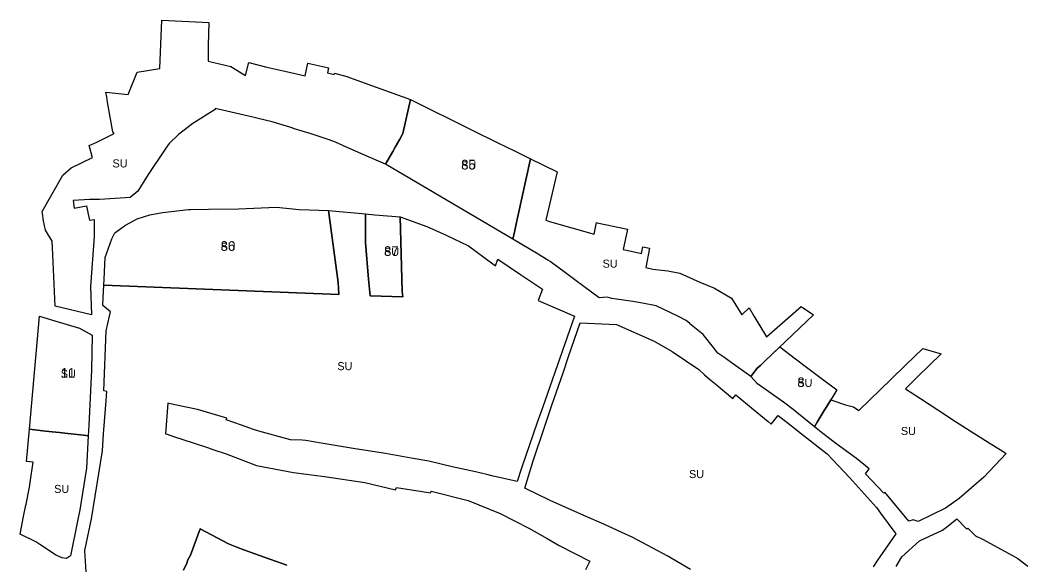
# Model space of a CAD drawing. Extents: x -545729 to -542727, y -1152416 to -1150952.
# Drawn here: x -544362 to -543736, y -1151290 to -1150952 of the extents above; entities that cross this region are included whole.
import ezdxf

# ---------------------------------------------------------------- set-up
doc = ezdxf.new("R2010")
doc.units = 0
for name, color, linetype in [('90480013', 7, 'Continuous'), ('90480023', 7, 'Continuous'), ('ID_navrh', 7, 'Continuous')]:
    doc.layers.add(name, color=color, linetype=linetype)

msp = doc.modelspace()

# ---------------------------------------------------------------- linework, layer by layer
at = {"layer": '90480013'}
for points in [[(-544281.81, -1151047.05), (-544286.37, -1151054.32), (-544288.69, -1151058.11), (-544293.42, -1151061.86), (-544302.75, -1151062.65), (-544312.53, -1151063.09), (-544318.75, -1151063.23), (-544328.84, -1151063.72), (-544328.3, -1151068.58), (-544320.64, -1151067.23), (-544319.5, -1151072.26), (-544318.73, -1151076.05), (-544315.73, -1151075.6), (-544315.73, -1151086.26), (-544317.99, -1151117.14), (-544317.35, -1151134.76), (-544340.06, -1151129.45), (-544341.74, -1151093.07), (-544341.92, -1151089.17), (-544346, -1151082.21), (-544347.27, -1151076.35), (-544347.85, -1151071.82), (-544348.07, -1151070.69), (-544342.02, -1151060.09), (-544335.18, -1151048.11), (-544330.07, -1151043.55), (-544316.92, -1151037.05), (-544317.11, -1151036.5), (-544318.86, -1151029.7), (-544314.12, -1151027.52), (-544303.38, -1151022.3), (-544304.25, -1151021.22), (-544307.45, -1151002.7), (-544308.03, -1150999.33), (-544308.64, -1150996.44), (-544294.75, -1150997.87), (-544289.15, -1150984.01), (-544275.03, -1150981.73), (-544273.79, -1150951.78), (-544244.73, -1150953.19), (-544245.06, -1150967.45), (-544245.1, -1150977.32), (-544231.07, -1150980.53), (-544221.95, -1150986.09), (-544219.85, -1150978.19), (-544208.58, -1150980.92), (-544197.54, -1150983.58), (-544184.95, -1150986.46), (-544183.27, -1150978.58), (-544173.93, -1150980.64), (-544170.39, -1150981.51), (-544171.09, -1150984.55), (-544166.85, -1150985.46), (-544166.56, -1150984.76), (-544159.03, -1150986.87), (-544145.91, -1150991.61), (-544119.4, -1151001.18), (-544124.2, -1151022.22), (-544126.02, -1151025.74), (-544128.94, -1151030.78), (-544130.55, -1151033.44), (-544135.01, -1151041.31), (-544148.39, -1151035.46), (-544158.87, -1151030.91), (-544166.12, -1151027.56), (-544169.93, -1151026.19), (-544181.06, -1151022.45), (-544192.4, -1151019.04), (-544192.34, -1151018.83), (-544205.37, -1151014.99), (-544214.12, -1151012.89), (-544217.31, -1151012.11), (-544227.99, -1151009.48), (-544236.21, -1151007.63), (-544240.8, -1151006.59), (-544240.68, -1151007.33), (-544254.64, -1151016.06), (-544263.54, -1151022.86), (-544269.25, -1151028.35), (-544269.15, -1151028.43), (-544271.34, -1151031.38)], [(-544055.89, -1151087.93), (-544054.67, -1151082.43), (-544054.09, -1151079.29), (-544052.62, -1151072.76), (-544045.08, -1151037.87), (-544028.46, -1151046.08), (-544035.43, -1151076.11), (-544033.15, -1151076.77), (-544019.44, -1151080.75), (-544005.53, -1151084.79), (-544004.04, -1151077.55), (-544003.66, -1151077.63), (-543984.82, -1151081.57), (-543987.45, -1151094.29), (-543982.64, -1151095.3), (-543976.17, -1151096.66), (-543975.37, -1151092.64), (-543971.13, -1151093.45), (-543973.4, -1151105.4), (-543969, -1151106.44), (-543959.81, -1151107.53), (-543952.27, -1151108.88), (-543939.98, -1151114.51), (-543930.93, -1151118.19), (-543920.31, -1151124.57), (-543913.95, -1151134.8), (-543909.27, -1151130.5), (-543906.23, -1151135.81), (-543898.64, -1151148.47), (-543877.03, -1151129.71), (-543869.4, -1151134.88), (-543899.56, -1151163.62), (-543902.11, -1151166.03), (-543904.57, -1151168.23), (-543905.39, -1151169.33), (-543905.59, -1151169.6), (-543908.28, -1151173.21), (-543920.47, -1151164.49), (-543925.06, -1151161.21), (-543928.69, -1151158.64), (-543931.37, -1151155.21), (-543937.89, -1151147.01), (-543946.19, -1151140.41), (-543946.15, -1151140.23), (-543948.46, -1151138.26), (-543953.58, -1151135.75), (-543966.97, -1151129.16), (-543975.61, -1151127.67), (-543981.61, -1151126.57), (-543994.53, -1151124.74), (-543997.51, -1151123.83), (-544002.35, -1151124.26), (-544016.68, -1151113.74), (-544023.35, -1151108.8), (-544032.91, -1151101.71), (-544034.19, -1151100.86), (-544037.9, -1151098.61), (-544040.31, -1151097.11)], [(-543787.44, -1151254.86), (-543804.52, -1151263.25), (-543807.5, -1151262.19), (-543810.15, -1151262.93), (-543825.07, -1151245.07), (-543825.8, -1151245.7), (-543837.14, -1151233.56), (-543834.93, -1151230.45), (-543842.74, -1151224.1), (-543853.29, -1151216.4), (-543856.58, -1151213.86), (-543863.57, -1151208.55), (-543868.86, -1151204.5), (-543867.05, -1151201.45), (-543862.83, -1151194.34), (-543861.63, -1151192.38), (-543858.68, -1151187.64), (-543849.54, -1151190.68), (-543844.56, -1151192), (-543841.19, -1151194.27), (-543821.4, -1151174.93), (-543812.37, -1151166.19), (-543801.55, -1151155.71), (-543790.2, -1151158.97), (-543804.94, -1151173.42), (-543812.4, -1151180.74), (-543803.08, -1151186.76), (-543792.17, -1151193.81), (-543781.24, -1151201.11), (-543769.93, -1151208.25), (-543758.65, -1151215.35), (-543755, -1151217.67), (-543753.31, -1151218.74), (-543749.81, -1151220.95), (-543763.74, -1151235.65), (-543778.92, -1151248.83)], [(-544359.55, -1151260.12), (-544358.15, -1151252.98), (-544358.05, -1151252.48), (-544355.95, -1151241.9), (-544354.93, -1151234.65), (-544353.73, -1151226.36), (-544357.7, -1151225.87), (-544355.92, -1151205.89), (-544350.99, -1151206.45), (-544345.94, -1151207.02), (-544341.87, -1151207.49), (-544341.87, -1151207.49), (-544337.35, -1151208), (-544333.95, -1151208.39), (-544322.47, -1151209.57), (-544319.5, -1151209.97), (-544320.53, -1151230.04), (-544324.7, -1151255.9), (-544326.16, -1151263.08), (-544330.54, -1151284.54), (-544332.89, -1151286.27), (-544335.78, -1151285.78), (-544339.82, -1151283.83), (-544349.44, -1151277.57), (-544352.01, -1151275.9), (-544361.72, -1151271.16)]]:
    msp.add_lwpolyline(points, close=True, dxfattribs=at)
for points in [[(-544320.51, -1151297.8), (-544321.55, -1151281.26), (-544317.48, -1151261.56), (-544310.68, -1151219.21), (-544309.91, -1151208.84), (-544308.39, -1151188.2), (-544307.9, -1151182.39), (-544309.75, -1151182.11), (-544308.38, -1151144.78), (-544306.28, -1151135.64), (-544305.65, -1151132.88), (-544310.47, -1151128.98), (-544310.22, -1151123.99), (-544309.84, -1151116.36), (-544163.89, -1151122.16), (-544164.4, -1151114.73), (-544170.42, -1151070.01), (-544147.35, -1151072.15), (-544147.41, -1151089.99), (-544145.59, -1151112.58), (-544144.43, -1151122.93), (-544124.29, -1151123.73), (-544124.6, -1151120.32), (-544124.61, -1151120.29), (-544124.62, -1151120.16), (-544125.96, -1151074.03), (-544109.42, -1151079.88), (-544097.44, -1151085.42), (-544083.41, -1151091.9), (-544068.3, -1151103.16), (-544066.7, -1151104.36), (-544065.3, -1151100.32), (-544051.12, -1151109.86), (-544037.55, -1151118.98), (-544040.27, -1151126.03), (-544017.79, -1151135.66), (-544037.55, -1151192.52), (-544040.78, -1151201.75), (-544050.68, -1151230.02), (-544053.24, -1151238.41), (-544061.61, -1151236.53), (-544068.15, -1151235), (-544072.2, -1151234), (-544079.19, -1151232.44), (-544093.63, -1151229.29), (-544108.2, -1151225.81), (-544119.1, -1151223.83), (-544119.1, -1151223.83), (-544135.07, -1151220.92), (-544155.03, -1151217.91), (-544174.98, -1151214.61), (-544184.48, -1151212.99), (-544186.63, -1151212.66), (-544194, -1151212.55), (-544213.68, -1151207.15), (-544216.85, -1151206), (-544224.38, -1151203.33), (-544233.8, -1151200.03), (-544233.48, -1151198.92), (-544251.76, -1151193.56), (-544265.8, -1151190.64), (-544270.06, -1151189.65), (-544271.45, -1151208.83), (-544270.44, -1151209), (-544266.53, -1151210.37), (-544254.27, -1151214.4), (-544244.94, -1151217.45), (-544242.14, -1151218.52), (-544233.95, -1151221.19), (-544215.15, -1151228.39), (-544192.11, -1151232.82), (-544172.85, -1151235.23), (-544147.79, -1151238.88), (-544128.88, -1151243.44), (-544128.27, -1151242.08), (-544112.23, -1151244.54), (-544107.01, -1151245.34), (-544106.61, -1151244.41), (-544083.61, -1151250.16), (-544063.84, -1151258.25), (-544046.02, -1151267.3), (-544034.7, -1151273.74), (-544027.27, -1151278.07), (-544008.14, -1151287.81), (-544010.85, -1151293.16)], [(-543945.7, -1151293.07), (-543954.29, -1151288.01), (-543958.85, -1151285.29), (-543959.76, -1151284.71), (-543981.96, -1151273), (-543988.26, -1151270.13), (-543999.56, -1151264.82), (-544009.98, -1151260.21), (-544032.78, -1151250.26), (-544048.52, -1151242.5), (-544043.35, -1151225.44), (-544036.38, -1151204.66), (-544032.04, -1151191.56), (-544024.64, -1151170.33), (-544021.35, -1151160.74), (-544014.15, -1151139.71), (-543991.7, -1151140.78), (-543968.25, -1151151.28), (-543957.16, -1151157.63), (-543940.51, -1151168.78), (-543937, -1151172.03), (-543933.97, -1151174.75), (-543929.88, -1151178.16), (-543919.49, -1151186.82), (-543917.59, -1151184.53), (-543906.64, -1151193.58), (-543897.46, -1151201.16), (-543895.65, -1151202.65), (-543891.6, -1151197.62), (-543891.32, -1151197.35), (-543881.27, -1151205.28), (-543876.76, -1151208.8), (-543860.89, -1151221.2), (-543853.8, -1151228.63), (-543846.98, -1151235.85), (-543830.34, -1151254.61), (-543827.85, -1151257.94), (-543818.28, -1151270.77), (-543829.61, -1151287.29), (-543832.4, -1151291.37)], [(-543818.17, -1151291.08), (-543814.61, -1151285.21), (-543803.59, -1151275.15), (-543789.27, -1151268.6), (-543786.91, -1151266.72), (-543780.39, -1151261.65), (-543774.22, -1151268.06), (-543774.16, -1151268.01), (-543773.53, -1151267.39), (-543768.94, -1151272.07), (-543764.46, -1151274.26), (-543745.85, -1151284.32), (-543745.85, -1151284.32), (-543742.56, -1151286.1), (-543736.38, -1151290.88)], [(-544196.3, -1151290.32), (-544213.09, -1151284.25), (-544222.9, -1151280.7), (-544227.2, -1151279.15), (-544232.38, -1151276.98), (-544249.96, -1151267.81), (-544256.01, -1151284.13), (-544257.66, -1151286.99), (-544258.33, -1151289.17), (-544260.35, -1151293.51)]]:
    msp.add_lwpolyline(points, dxfattribs=at)
at = {"layer": '90480023'}
for points in [[(-544054.67, -1151082.43), (-544055.89, -1151087.93), (-544135.01, -1151041.31), (-544130.55, -1151033.44), (-544128.94, -1151030.78), (-544126.02, -1151025.74), (-544124.2, -1151022.22), (-544119.4, -1151001.18), (-544081.2, -1151020.04), (-544065.22, -1151027.93), (-544054.92, -1151033.02), (-544045.08, -1151037.87), (-544045.08, -1151037.87), (-544052.62, -1151072.76), (-544054.09, -1151079.29)], [(-544273.39, -1151071.2), (-544257.32, -1151069.5), (-544255.79, -1151069.46), (-544244.82, -1151069.16), (-544226.12, -1151068.98), (-544202.6, -1151068.01), (-544188.57, -1151069.43), (-544182.27, -1151069.63), (-544170.42, -1151070.01), (-544164.4, -1151114.73), (-544163.89, -1151122.16), (-544309.84, -1151116.36), (-544309.66, -1151112.71), (-544308.93, -1151099.17), (-544304.91, -1151087.65), (-544302.97, -1151083.97), (-544296.35, -1151079.23), (-544289.05, -1151075.26), (-544281.31, -1151072.64)], [(-544141.57, -1151072.66), (-544125.96, -1151074.03), (-544124.62, -1151120.16), (-544124.61, -1151120.29), (-544124.6, -1151120.32), (-544124.29, -1151123.73), (-544144.43, -1151122.93), (-544145.59, -1151112.58), (-544147.41, -1151089.99), (-544147.35, -1151072.15)], [(-544337.35, -1151208), (-544341.87, -1151207.49), (-544341.87, -1151207.49), (-544345.94, -1151207.02), (-544350.99, -1151206.45), (-544355.92, -1151205.89), (-544349.7, -1151135.7), (-544340.13, -1151138.59), (-544324.86, -1151143.2), (-544317.04, -1151147.53), (-544317.52, -1151169.14), (-544319, -1151203.45), (-544319.5, -1151209.97), (-544322.47, -1151209.57), (-544333.95, -1151208.39)], [(-543858.68, -1151187.64), (-543861.63, -1151192.38), (-543862.83, -1151194.34), (-543867.05, -1151201.45), (-543868.86, -1151204.5), (-543881.98, -1151193.72), (-543888.04, -1151189.17), (-543904.16, -1151177.72), (-543908.28, -1151173.21), (-543905.59, -1151169.6), (-543905.39, -1151169.33), (-543904.57, -1151168.23), (-543902.11, -1151166.03), (-543899.56, -1151163.62), (-543890.28, -1151154.78), (-543880.55, -1151162.13), (-543872.12, -1151168.49), (-543863.71, -1151174.83), (-543854.87, -1151181.51)]]:
    msp.add_lwpolyline(points, close=True, dxfattribs=at)
msp.add_lwpolyline([(-544260.35, -1151293.51), (-544258.33, -1151289.17), (-544257.66, -1151286.99), (-544256.01, -1151284.13), (-544249.96, -1151267.81), (-544232.38, -1151276.98), (-544227.2, -1151279.15), (-544222.9, -1151280.7), (-544213.09, -1151284.25), (-544196.3, -1151290.32)], dxfattribs=at)

# ---------------------------------------------------------------- texts
at = {"layer": '90480013'}
for rotation, p in [(0, (-544304.39, -1151043.27)), (360, (-544000.27, -1151105.54)), (0, (-544164.85, -1151169.2)), (360, (-543815.16, -1151209.48)), (0, (-543946.63, -1151236.24)), (360, (-544340.61, -1151245.47))]:
    msp.add_text('SU', height=5, rotation=rotation, dxfattribs=at).set_placement(p)
at = {"layer": '90480023'}
for rotation, p in [(0, (-544088.01, -1151044.55)), (0, (-544237.27, -1151095.08)), (0, (-544135.85, -1151098.22)), (360, (-544336.48, -1151173.9)), (0, (-543879.4, -1151179.64))]:
    msp.add_text('SU', height=5, rotation=rotation, dxfattribs=at).set_placement(p)
at = {"layer": 'ID_navrh'}
for s, rotation, p in [('85', 0, (-544088.01, -1151044.55)), ('86', 0, (-544237.27, -1151095.08)), ('87', 0, (-544135.85, -1151098.22)), ('8', 360, (-543879.4, -1151179.64))]:
    msp.add_text(s, height=6, rotation=rotation, dxfattribs=at).set_placement(p)
msp.add_text('11', height=6, dxfattribs=at).set_placement((-544336.48, -1151173.9))

doc.saveas('drawing.dxf')
